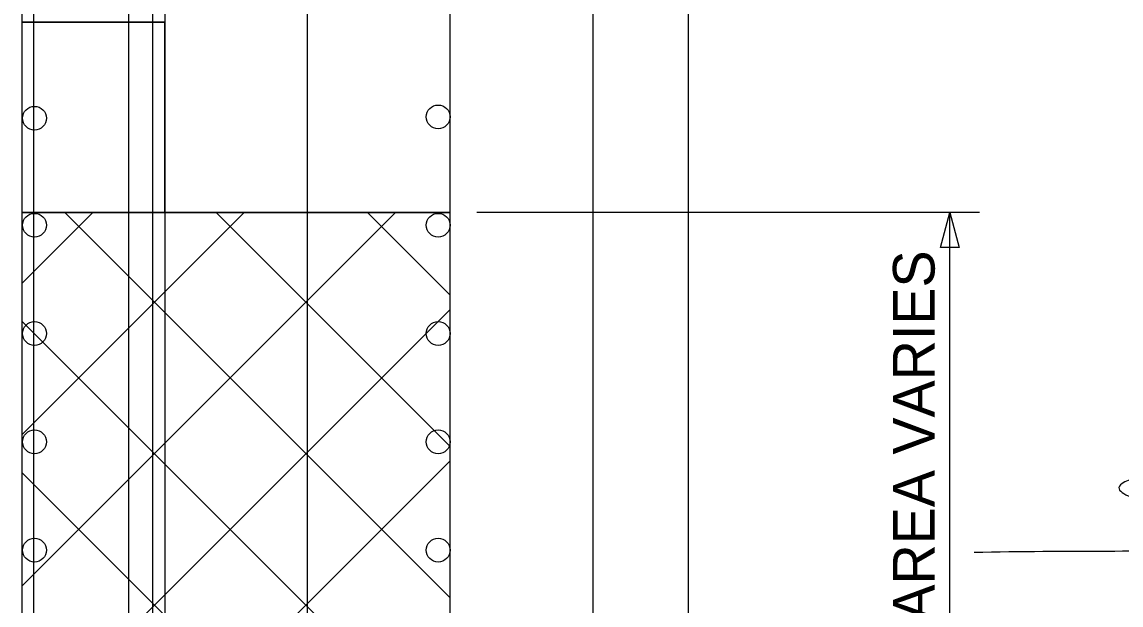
# Model space of a CAD drawing. Extents: x 16731 to 18475, y 7003 to 8262.
# Drawn here: x 17017.2 to 17202, y 7886.8 to 7984.8 of the extents above; entities that cross this region are included whole.
import ezdxf

# ---------------------------------------------------------------- set-up
doc = ezdxf.new("R2010")
doc.units = 0
for name, color, linetype in [('ALI_LEGAL_EX', 7, 'Continuous'), ('MT_SCRATCH_LEVEL_A', 7, 'Continuous'), ('PAVT_EDGE_EX', 7, 'Continuous'), ('TRAFFIC_SIGNS_PR', 7, 'Continuous'), ('TYPICAL_TEXT_DIMEN_PR', 7, 'Continuous')]:
    doc.layers.add(name, color=color, linetype=linetype)

msp = doc.modelspace()

# ---------------------------------------------------------------- linework, layer by layer
at = {"layer": 'ALI_LEGAL_EX'}
for p, q in [((17019.24, 7388.68), (17019.24, 8211.76)), ((17039.24, 7388.68), (17039.24, 8211.76)), ((17065.24, 7388.68), (17065.24, 8211.76)), ((17089.24, 7388.68), (17089.24, 8211.76))]:
    msp.add_line(p, q, dxfattribs=at)
for points in [[(17019.24, 7888.68), (17019.24, 7913.68)], [(17039.24, 7888.68), (17039.24, 7913.68)], [(17065.24, 7888.68), (17065.24, 7913.68)], [(17089.24, 7888.68), (17089.24, 7913.68)]]:
    msp.add_lwpolyline(points, dxfattribs=at)
at = {"layer": 'MT_SCRATCH_LEVEL_A'}
for p, q in [((17017.24, 7984.81), (17041.24, 7984.81)), ((17017.24, 7984.81), (17017.24, 7806.97)), ((17041.24, 7984.81), (17017.24, 7984.81)), ((17017.24, 7984.81), (17017.24, 7952.75)), ((17041.24, 7984.81), (17041.24, 7952.75)), ((17041.24, 7952.75), (17041.24, 7984.81)), ((17017.24, 7952.75), (17089.24, 7952.75)), ((17089.24, 7952.75), (17017.24, 7952.75)), ((17017.24, 7952.75), (17017.24, 7839.03)), ((17017.24, 7952.75), (17041.24, 7952.75)), ((17017.24, 7940.85), (17029.14, 7952.75)), ((17017.24, 7915.4), (17054.6, 7952.75)), ((17017.24, 7889.94), (17080.05, 7952.75)), ((17089.24, 7887.94), (17024.43, 7952.75)), ((17089.24, 7913.4), (17049.88, 7952.75)), ((17089.24, 7938.86), (17075.34, 7952.75)), ((17017.24, 7864.48), (17089.24, 7936.48)), ((17089.24, 7862.49), (17017.24, 7934.49)), ((17017.24, 7839.03), (17089.24, 7911.03)), ((17087.24, 7839.03), (17017.24, 7909.03))]:
    msp.add_line(p, q, dxfattribs=at)
at = {"layer": 'PAVT_EDGE_EX'}
for p, q in [((17035.15, 8262.34), (17035.15, 7433.15)), ((17017.24, 8211.76), (17017.24, 7353.85)), ((17041.24, 8211.76), (17041.24, 7353.85)), ((17113.24, 8211.76), (17113.24, 7353.85)), ((17129.24, 8211.76), (17129.24, 7353.85))]:
    msp.add_line(p, q, dxfattribs=at)
at = {"layer": 'TRAFFIC_SIGNS_PR'}
for centre in [(17019.34, 7968.63), (17087.21, 7968.85), (17019.34, 7950.63), (17087.21, 7950.63), (17019.34, 7932.42), (17087.21, 7932.42), (17019.34, 7914.2), (17087.21, 7914.2), (17019.34, 7895.99), (17087.21, 7895.99)]:
    msp.add_circle(centre, 2, dxfattribs=at)
at = {"layer": 'TYPICAL_TEXT_DIMEN_PR'}
for p, q in [((17178.24, 7952.75), (17093.74, 7952.75)), ((17171.67, 7946.89), (17173.24, 7952.75)), ((17173.24, 7839.03), (17173.24, 7952.75)), ((17173.24, 7952.75), (17174.81, 7946.89)), ((17173.24, 7946.89), (17171.67, 7946.89)), ((17174.81, 7946.89), (17173.24, 7946.89))]:
    msp.add_line(p, q, dxfattribs=at)
msp.add_open_spline([(17259.28, 7910.95), (17199.04, 7910.59), (17199.04, 7903.32), (17224.22, 7903.32), (17224.22, 7894.79), (17192.85, 7895.99), (17177.35, 7895.57)], degree=3, dxfattribs=at)

# ---------------------------------------------------------------- texts
msp.add_text('WORK AREA VARIES', height=7, rotation=90, dxfattribs=at).set_placement((17170.68, 7852.25))

doc.saveas('drawing.dxf')
